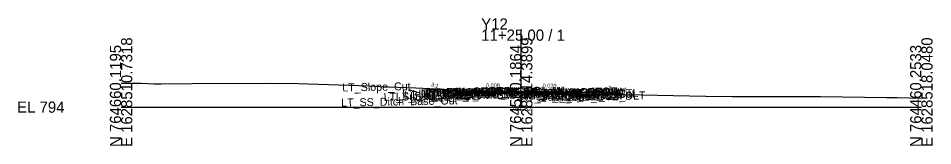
# Model space of a CAD drawing. Extents: x -26 to 203, y -10 to 3521.
# Drawn here: x -25.7 to 202.8, y 2490.3 to 2522.3 of the extents above; entities that cross this region are included whole.
import ezdxf

# ---------------------------------------------------------------- set-up
doc = ezdxf.new("R2010")
doc.units = 0
for name, color, linetype in [('Default', 7, 'Continuous'), ('Exist Cross Section Cell', 7, 'Continuous'), ('Exist XS Center Line Elevation Label', 7, 'Continuous'), ('Exist XS Ground Line', 7, 'Continuous'), ('Prop CMT Conc Surface', 7, 'Continuous'), ('Prop CMT Concrete Structures', 7, 'Continuous'), ('Prop CMT Pvmt Course 1', 7, 'Continuous'), ('Prop CMT Pvmt Course 1 Wedge', 7, 'Continuous'), ('Prop CMT Pvmt Course 2', 7, 'Continuous'), ('Prop CMT Pvmt Course 2 Wedge', 7, 'Continuous'), ('Prop CMT Pvmt Course 3', 7, 'Continuous'), ('Prop CMT Pvmt Surface', 7, 'Continuous'), ('Prop CMT Pvmt Wedge Surface 1', 7, 'Continuous'), ('Prop CMT Pvmt Wedge Surface 2', 7, 'Continuous'), ('Prop CMT Pvmt Wedge Surface 3', 7, 'Continuous'), ('Prop CMT Shld Paved Course 3', 7, 'Continuous'), ('Prop CMT Slope Grass', 7, 'Continuous'), ('Prop CMT Subgrade Earthwork', 7, 'Continuous'), ('Prop XS SE Text', 7, 'Continuous'), ('Prop XS Side Slope Text', 7, 'Continuous'), ('Scratch_Level_0', 7, 'Continuous')]:
    doc.layers.add(name, color=color, linetype=linetype)

msp = doc.modelspace()

# ---------------------------------------------------------------- linework, layer by layer
at = {"layer": 'Exist Cross Section Cell'}
for p, q in [((100, 2500), (100, 2519.46)), ((0, 2500), (100, 2500)), ((100, 2500), (200, 2500))]:
    msp.add_line(p, q, dxfattribs=at)
at = {"layer": 'Exist XS Ground Line'}
msp.add_lwpolyline([(0, 2505.98), (5.02, 2505.99), (8.23, 2505.84), (10.05, 2505.85), (17.74, 2505.92), (37.26, 2506.05), (44.24, 2505.9), (51.8, 2505.64), (62.08, 2505.33), (64.57, 2505.16), (73.64, 2504.87), (77.15, 2504.67), (79.4, 2504.48), (86.6, 2503.86), (97.6, 2503.66), (100, 2503.62), (113.8, 2503.37), (125.9, 2503.18), (129.95, 2503.12), (146.18, 2502.75), (152.71, 2502.65), (174.78, 2502.67), (191.28, 2502.43), (193.93, 2502.41), (200, 2502.23)], dxfattribs=at)
at = {"layer": 'Prop CMT Conc Surface'}
for points in [[(85.9, 2503.89), (84.9, 2503.8), (83.9, 2503.89)], [(114.15, 2503.74), (115.15, 2503.65), (116.15, 2503.74)]]:
    msp.add_lwpolyline(points, dxfattribs=at)
at = {"layer": 'Prop CMT Concrete Structures'}
for points in [[(85.9, 2503.89), (84.9, 2503.8), (83.9, 2503.89)], [(83.9, 2503.89), (83.9, 2503.3), (85.9, 2503.3)], [(85.9, 2503.3), (85.9, 2503.89)], [(114.15, 2503.74), (115.15, 2503.65), (116.15, 2503.74)], [(116.15, 2503.74), (116.15, 2503.15), (114.15, 2503.15)], [(114.15, 2503.15), (114.15, 2503.74)]]:
    msp.add_lwpolyline(points, dxfattribs=at)
at = {"layer": 'Prop CMT Pvmt Course 1'}
for points in [[(100, 2504.02), (85.9, 2503.89)], [(85.9, 2503.89), (85.9, 2503.64)], [(85.9, 2503.64), (100, 2503.77)], [(100, 2504.02), (86.9, 2503.9)], [(86.9, 2503.9), (86.9, 2503.77)], [(86.9, 2503.77), (100, 2503.89)], [(100, 2503.89), (100, 2504.02)], [(100, 2503.77), (100, 2504.02)], [(100, 2504.02), (113.15, 2503.76)], [(100, 2503.89), (100, 2504.02)], [(100, 2504.02), (114.15, 2503.74)], [(100, 2503.77), (100, 2504.02)], [(113.15, 2503.63), (100, 2503.89)], [(114.15, 2503.49), (100, 2503.77)], [(113.15, 2503.76), (113.15, 2503.63)], [(114.15, 2503.74), (114.15, 2503.49)]]:
    msp.add_lwpolyline(points, dxfattribs=at)
at = {"layer": 'Prop CMT Pvmt Course 1 Wedge'}
for points in [[(89.9, 2503.8), (97.6, 2503.87)], [(100, 2503.77), (97.6, 2503.75), (94.39, 2503.72), (89.9, 2503.8)], [(97.6, 2503.87), (100, 2503.89)], [(100, 2503.89), (100, 2503.77)], [(100, 2503.89), (113.15, 2503.63)], [(100, 2503.77), (100, 2503.89)], [(113.15, 2503.51), (100, 2503.77)], [(113.15, 2503.63), (113.15, 2503.51)]]:
    msp.add_lwpolyline(points, dxfattribs=at)
at = {"layer": 'Prop CMT Pvmt Course 2'}
for points in [[(100, 2503.77), (85.9, 2503.64)], [(85.9, 2503.64), (85.9, 2503.3)], [(85.9, 2503.3), (100, 2503.44)], [(100, 2503.44), (100, 2503.77)], [(100, 2503.44), (100, 2503.77)], [(100, 2503.77), (114.15, 2503.49)], [(114.15, 2503.15), (100, 2503.44)], [(114.15, 2503.49), (114.15, 2503.15)]]:
    msp.add_lwpolyline(points, dxfattribs=at)
at = {"layer": 'Prop CMT Pvmt Course 2 Wedge'}
for points in [[(94.39, 2503.72), (97.6, 2503.75)], [(100, 2503.62), (97.6, 2503.66), (94.39, 2503.72)], [(97.6, 2503.75), (100, 2503.77)], [(100, 2503.77), (100, 2503.62)], [(100, 2503.77), (113.15, 2503.51)], [(100, 2503.62), (100, 2503.77)], [(113.15, 2503.38), (100, 2503.62)], [(113.15, 2503.51), (113.15, 2503.38)]]:
    msp.add_lwpolyline(points, dxfattribs=at)
at = {"layer": 'Prop CMT Pvmt Course 3'}
msp.add_line((116.15, 2503.15), (116.65, 2503.15), dxfattribs=at)
for points in [[(100, 2503.44), (85.9, 2503.3)], [(85.9, 2503.3), (85.9, 2502.97)], [(85.9, 2502.97), (86.9, 2502.98)], [(100, 2503.1), (100, 2503.44)], [(100, 2503.44), (114.15, 2503.15)], [(100, 2503.1), (100, 2503.44)], [(114.15, 2502.82), (113.15, 2502.84)], [(114.15, 2503.15), (114.15, 2502.82)]]:
    msp.add_lwpolyline(points, dxfattribs=at)
at = {"layer": 'Prop CMT Pvmt Surface'}
for points in [[(100, 2504.02), (85.9, 2503.89)], [(100, 2504.02), (86.9, 2503.9)], [(100, 2504.02), (114.15, 2503.74)], [(100, 2504.02), (113.15, 2503.76)]]:
    msp.add_lwpolyline(points, dxfattribs=at)
at = {"layer": 'Prop CMT Pvmt Wedge Surface 1'}
for points in [[(85.9, 2503.64), (85.9, 2503.89)], [(86.9, 2503.77), (86.9, 2503.9)], [(100, 2503.89), (86.9, 2503.77)], [(100, 2503.89), (113.15, 2503.63)], [(113.15, 2503.63), (113.15, 2503.76)], [(114.15, 2503.49), (114.15, 2503.74)]]:
    msp.add_lwpolyline(points, dxfattribs=at)
at = {"layer": 'Prop CMT Pvmt Wedge Surface 2'}
for points in [[(85.9, 2503.64), (85.9, 2503.89)], [(86.9, 2503.65), (86.9, 2503.9)], [(100, 2503.77), (86.9, 2503.65)], [(100, 2503.77), (100, 2504.02)], [(100, 2503.77), (100, 2504.02)], [(100, 2503.77), (100, 2504.02)], [(100, 2503.77), (100, 2504.02)], [(100, 2503.77), (113.15, 2503.51)], [(113.15, 2503.51), (113.15, 2503.76)], [(114.15, 2503.49), (114.15, 2503.74)]]:
    msp.add_lwpolyline(points, dxfattribs=at)
at = {"layer": 'Prop CMT Pvmt Wedge Surface 3'}
for points in [[(85.9, 2503.3), (85.9, 2503.89)], [(86.9, 2503.31), (86.9, 2503.9)], [(100, 2503.44), (86.9, 2503.31)], [(100, 2503.44), (100, 2504.02)], [(100, 2503.44), (100, 2504.02)], [(100, 2503.44), (100, 2504.02)], [(100, 2503.44), (100, 2504.02)], [(100, 2503.44), (113.15, 2503.17)], [(113.15, 2503.17), (113.15, 2503.76)], [(114.15, 2503.15), (114.15, 2503.74)]]:
    msp.add_lwpolyline(points, dxfattribs=at)
at = {"layer": 'Prop CMT Shld Paved Course 3'}
for p, q in [((83.06, 2502.96), (85.9, 2502.97)), ((116.99, 2502.81), (114.15, 2502.82))]:
    msp.add_line(p, q, dxfattribs=at)
for points in [[(85.9, 2503.3), (83.9, 2503.3), (83.4, 2503.3), (83.06, 2502.96)], [(114.15, 2503.15), (116.65, 2503.15), (116.65, 2503.15), (116.99, 2502.81)]]:
    msp.add_lwpolyline(points, dxfattribs=at)
at = {"layer": 'Prop CMT Slope Grass'}
for points in [[(83.9, 2503.89), (78.9, 2503.99), (76.84, 2504.68)], [(116.15, 2503.74), (121.15, 2503.84), (122.99, 2503.22)]]:
    msp.add_lwpolyline(points, dxfattribs=at)
at = {"layer": 'Prop CMT Subgrade Earthwork'}
for p, q in [((83.06, 2502.96), (82.1, 2503.92)), ((85.9, 2502.97), (83.06, 2502.96)), ((114.15, 2502.82), (116.99, 2502.81)), ((116.99, 2502.81), (117.95, 2503.77))]:
    msp.add_line(p, q, dxfattribs=at)
for points in [[(86.9, 2502.98), (85.9, 2502.97)], [(86.9, 2502.98), (86.92, 2503.85)], [(113.15, 2502.84), (113.14, 2503.38)], [(113.15, 2502.84), (114.15, 2502.82)]]:
    msp.add_lwpolyline(points, dxfattribs=at)

# ---------------------------------------------------------------- texts
at = {"layer": 'Default'}
msp.add_text('-', height=0.0001, dxfattribs=at).set_placement((0, 2500))
at = {"layer": 'Exist Cross Section Cell'}
for s, p in [('Y12', (90, 2519.46)), ('11+25.00 / 1', (90, 2516.66)), ('EL 794', (-26, 2498.6))]:
    msp.add_text(s, height=2.8, dxfattribs=at).set_placement(p)
for s, p in [('E 1628510.7318', (2.8, 2490)), ('E 1628514.3899', (102.8, 2490)), ('E 1628518.0480', (202.8, 2490)), ('N 764660.1195', (0, 2490)), ('N 764560.1864', (100, 2490)), ('N 764460.2533', (200, 2490))]:
    msp.add_text(s, height=2.8, rotation=90, dxfattribs=at).set_placement(p)
at = {"layer": 'Exist XS Center Line Elevation Label'}
msp.add_text('797.62', height=1.2, dxfattribs=at).set_placement((97.51, 2499.02))
at = {"layer": 'Prop XS SE Text'}
for s, rotation, p in [('0.009', 0.5395, (91.2, 2504.94)), ('0.020', 358.8542, (105.35, 2504.91))]:
    msp.add_text(s, height=1, rotation=rotation, dxfattribs=at).set_placement(p)
at = {"layer": 'Prop XS Side Slope Text'}
for p in [(77.35, 2505.29), (121.56, 2504.49)]:
    msp.add_text('3:1', height=1, rotation=341.5651, dxfattribs=at).set_placement(p)
at = {"layer": 'Scratch_Level_0'}
for s, p in [('LT_Slope_Cut', (55.29, 2503.92)), ('LT_PV2_OEEOP_W', (74.34, 2502.4)), ('LT_PV1_OEEOP_W', (74.91, 2502.53)), ('LT_PS2_OEOP', (75.9, 2502.44)), ('LT_PV2_OEOT', (76.1, 2502.44)), ('LT_PV1_OEOT', (76.66, 2502.7)), ('LT_PS1_OEOP', (76.73, 2502.7)), ('LT_PV1_OEEOP', (76.8, 2502.69)), ('RT_PV1_PGL_W', (89.86, 2502.69)), ('LT_PV1_PGL_W', (89.91, 2502.69)), ('PV2_PGL', (93.93, 2502.65)), ('PV1_PGL', (94.49, 2502.91)), ('RT_PV2_OEEOP_W', (100.54, 2502.25)), ('RT_PV1_OEEOP_W', (101.11, 2502.39)), ('RT_PV1_OEEOP', (103, 2502.55)), ('RT_PV1_OEOT', (104.87, 2502.55)), ('RT_PS1_OEOP', (104.93, 2502.55)), ('LT_SS_Ditch_Base_Out', (55, 2500.13)), ('LT_Sub_OSS_DLT', (65.64, 2501.57)), ('LT_Sub_Trench_Out', (68.69, 2501.63)), ('LT_GS_OS_CTL', (70.29, 2502.27)), ('LT_PS3_Shelf_Out', (70.81, 2502)), ('LT_PV3_OEEOP_W', (74.34, 2502.06)), ('LT_PS3_OEOP', (75.56, 2502.1)), ('LT_Sub_OEOT', (76, 2501.77)), ('LT_PV3_OEOT', (76.1, 2502.11)), ('Sub_PGL', (93.83, 2501.98)), ('PV3_PGL', (93.93, 2502.31)), ('RT_Sub_Trench_Out', (99.77, 2501.47)), ('RT_PV3_OEEOP_W', (100.54, 2501.92)), ('RT_PS3_Shelf_Out', (101.21, 2501.85)), ('RT_Sub_OEOT', (104.2, 2501.62)), ('RT_PV2_OEOT', (104.3, 2502.29)), ('RT_PV3_OEOT', (104.3, 2501.96)), ('RT_PS2_OEOP', (104.62, 2502.29)), ('RT_PS3_OEOP', (104.96, 2501.95)), ('RT_Sub_OSS_DLT', (107.58, 2501.48)), ('RT_GS_OS_CTL', (108.5, 2502.12)), ('RT_Slope_Cut', (110.88, 2502.04))]:
    msp.add_text(s, height=2, rotation=1.1458, dxfattribs=at).set_placement(p)

doc.saveas('drawing.dxf')
